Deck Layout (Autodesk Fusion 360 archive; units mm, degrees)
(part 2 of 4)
sketch "Reload Launch Plunger" plane through (0, 0, 8) normal (0, 0, 1) x axis (-1, 0, 0)
  line L1 (-360.8217, -46.399) -> (-358.0535, -46.4059)
  line L2 (-363.9178, -46.3914) -> (-361.0138, -46.3986)
  line L3 (-361.0035, -43.4046) -> (-362.68, -43.397)
  line L4 (-358.0433, -43.4179) -> (-360.8112, -43.4054)
  line L5 (-360.8495, -54.399) -> (-358.0816, -54.4058)
  line L6 (-363.9457, -54.3914) -> (-361.0418, -54.3985)
  line L7 (-361.0313, -51.4045) -> (-363.9352, -51.3914)
  line L8 (-358.071, -51.4179) -> (-360.8392, -51.4054)
  line L9 (-337.909, -43.4822) -> (-343.909, -43.4612)
  line L10 (-340.8631, -46.4708) -> (-337.92, -46.4822)
  line L11 (-343.8396, -46.4594) -> (-340.9768, -46.4704)
  line L12 (-343.9473, -54.4612) -> (-337.9474, -54.4821)
  line L13 (-341.0041, -51.4729) -> (-343.9361, -51.4612)
  line L14 (-338.0323, -51.4848) -> (-340.8681, -51.4735)
  line L15 (-332.4666, -38.0012) -> (-332.3898, -38.0014)
  line L16 (-332.4666, -35.9861) -> (-332.4666, -38.0012)
  line L17 (-369.4666, -35.9861) -> (-332.4666, -35.9861)
  line L18 (-369.4666, -62.0013) -> (-369.4666, -35.9861)
  line L19 (-332.4666, -62.0013) -> (-369.4666, -62.0013)
  line L20 (-332.4666, -60.0013) -> (-332.4666, -62.0013)
  line L21 (-332.3898, -38.0014) -> (-332.4666, -60.0013)
  line L22 (-369.5336, -53.1093) -> (-390.5336, -53.1093)
  line L23 (-390.5336, -45.1093) -> (-369.5336, -45.1093)
  line L24 (-371.5336, -45.1093) -> (-390.5336, -45.1093)
  line L25 (-384.5336, -45.1093) -> (-384.5336, -53.1093)
  line L26 (-387.5336, -45.1093) -> (-387.5336, -53.1093)
  line L27 (-371.5336, -45.1093) -> (-371.5336, -53.1093)
  line L28 (-384.5336, -45.1093) -> (-384.5336, -53.1093)
  line L29 (-390.5336, -53.1093) -> (-390.5336, -45.1093)
  line L30 (-369.5336, -45.1093) -> (-369.5336, -53.1093)
  line L31 (-371.5336, -53.1093) -> (-390.5336, -53.1093)
  line L32 (-332.4666, -35.9861) -> (-332.4666, -38.0012)
  line L33 (-361.0035, -43.4046) -> (-362.68, -43.397)
  line L34 (-332.4666, -38.0012) -> (-332.3898, -38.0014)
  line L35 (-358.071, -51.4179) -> (-360.8392, -51.4054)
  line L36 (-338.0323, -51.4848) -> (-340.8681, -51.4735)
  line L37 (-361.0313, -51.4045) -> (-363.9352, -51.3914)
  line L38 (-387.5336, -45.1093) -> (-387.5336, -53.1093)
  line L39 (-369.5336, -53.1093) -> (-390.5336, -53.1093)
  line L40 (-390.5336, -53.1093) -> (-390.5336, -45.1093)
  line L41 (-360.8217, -46.399) -> (-358.0535, -46.4059)
  line L42 (-337.909, -43.4822) -> (-343.909, -43.4612)
  line L43 (-332.4666, -62.0013) -> (-369.4666, -62.0013)
  line L44 (-369.4666, -35.9861) -> (-332.4666, -35.9861)
  line L45 (-332.3898, -38.0014) -> (-332.4666, -60.0013)
  line L46 (-360.8495, -54.399) -> (-358.0816, -54.4058)
  line L47 (-343.9473, -54.4612) -> (-337.9474, -54.4821)
  line L48 (-340.8631, -46.4708) -> (-337.92, -46.4822)
  line L49 (-369.4666, -62.0013) -> (-369.4666, -35.9861)
  line L50 (-363.9178, -46.3914) -> (-361.0138, -46.3986)
  line L51 (-358.0433, -43.4179) -> (-360.8112, -43.4054)
  line L52 (-341.0041, -51.4729) -> (-343.9361, -51.4612)
  line L53 (-363.9457, -54.3914) -> (-361.0418, -54.3985)
  line L54 (-343.8396, -46.4594) -> (-340.9768, -46.4704)
  line L55 (-332.4666, -60.0013) -> (-332.4666, -62.0013)
  line L56 (-387.5336, -45.1093) -> (-387.5336, -53.1093)
  line L57 (-384.5336, -45.1093) -> (-384.5336, -53.1093)
  line L58 (-371.5336, -53.1093) -> (-390.5336, -53.1093)
  line L59 (-369.5336, -53.1093) -> (-390.5336, -53.1093)
  line L60 (-371.5336, -45.1093) -> (-371.5336, -53.1093)
  line L61 (-384.5336, -45.1093) -> (-384.5336, -53.1093)
  line L62 (-390.5336, -45.1093) -> (-369.5336, -45.1093)
  line L63 (-387.5336, -45.1093) -> (-387.5336, -53.1093)
  line L64 (-390.5336, -53.1093) -> (-390.5336, -45.1093)
  line L65 (-390.5336, -53.1093) -> (-390.5336, -45.1093)
  line L66 (-369.5336, -53.1093) -> (-390.5336, -53.1093)
  line L67 (-371.5336, -45.1093) -> (-390.5336, -45.1093)
  line L68 (-418, -48.8509) -> (-390.6679, -48.8509)
  arc A1 centre (-360.9141, -44.9019) radius 1.5 clockwise from (-360.8217, -46.399) to (-361.0138, -46.3986)
  arc A2 centre (-363.9141, -44.8914) radius 1.5 clockwise from (-363.9178, -46.3914) to (-365.3409, -44.4285)
  arc A3 centre (-364.4071, -42.8897) radius 1.8 clockwise from (-365.3409, -44.4285) to (-362.68, -43.397)
  arc A4 centre (-360.9141, -44.9019) radius 1.5 clockwise from (-361.0035, -43.4046) to (-360.8112, -43.4054)
  arc A5 centre (-357.9141, -44.9124) radius 1.5 clockwise from (-358.0433, -43.4179) to (-358.0535, -46.4059)
  arc A6 centre (-357.942, -52.9123) radius 1.5 clockwise from (-358.071, -51.4179) to (-358.0816, -54.4058)
  arc A7 centre (-360.942, -52.9018) radius 1.5 clockwise from (-360.8495, -54.399) to (-361.0418, -54.3985)
  arc A8 centre (-363.942, -52.8914) radius 1.5 clockwise from (-363.9457, -54.3914) to (-363.9352, -51.3914)
  arc A9 centre (-360.942, -52.9018) radius 1.5 clockwise from (-361.0313, -51.4045) to (-360.8392, -51.4054)
  circle C1 centre (-348.9491, -54.9437) radius 1.8
  arc A10 centre (-343.9142, -44.9612) radius 1.5 clockwise from (-343.8396, -46.4594) to (-343.909, -43.4612)
  arc A11 centre (-337.9142, -44.9822) radius 1.5 clockwise from (-337.909, -43.4822) to (-337.92, -46.4822)
  arc A12 centre (-340.9142, -44.9717) radius 1.5 clockwise from (-340.8631, -46.4708) to (-340.9768, -46.4704)
  arc A13 centre (-343.9421, -52.9612) radius 1.5 clockwise from (-343.9473, -54.4612) to (-343.9361, -51.4612)
  arc A14 centre (-340.9421, -52.9717) radius 1.5 clockwise from (-341.0041, -51.4729) to (-340.8681, -51.4735)
  arc A15 centre (-337.9421, -52.9821) radius 1.5 clockwise from (-338.0323, -51.4848) to (-337.9474, -54.4821)
  arc A16 centre (-340.9142, -44.9717) radius 1.5 clockwise from (-340.8631, -46.4708) to (-340.9768, -46.4704)
  circle C2 centre (-348.9491, -54.9437) radius 1.8
  arc A17 centre (-343.9421, -52.9612) radius 1.5 clockwise from (-343.9473, -54.4612) to (-343.9361, -51.4612)
  arc A18 centre (-360.9141, -44.9019) radius 1.5 clockwise from (-360.8217, -46.399) to (-361.0138, -46.3986)
  arc A19 centre (-340.9421, -52.9717) radius 1.5 clockwise from (-341.0041, -51.4729) to (-340.8681, -51.4735)
  arc A20 centre (-360.942, -52.9018) radius 1.5 clockwise from (-361.0313, -51.4045) to (-360.8392, -51.4054)
  arc A21 centre (-364.4071, -42.8897) radius 1.8 clockwise from (-365.3409, -44.4285) to (-362.68, -43.397)
  arc A22 centre (-360.9141, -44.9019) radius 1.5 clockwise from (-361.0035, -43.4046) to (-360.8112, -43.4054)
  arc A23 centre (-360.942, -52.9018) radius 1.5 clockwise from (-360.8495, -54.399) to (-361.0418, -54.3985)
  arc A24 centre (-357.9141, -44.9124) radius 1.5 clockwise from (-358.0433, -43.4179) to (-358.0535, -46.4059)
  arc A25 centre (-337.9421, -52.9821) radius 1.5 clockwise from (-338.0323, -51.4848) to (-337.9474, -54.4821)
  arc A26 centre (-363.9141, -44.8914) radius 1.5 clockwise from (-363.9178, -46.3914) to (-365.3409, -44.4285)
  arc A27 centre (-363.942, -52.8914) radius 1.5 clockwise from (-363.9457, -54.3914) to (-363.9352, -51.3914)
  arc A28 centre (-357.942, -52.9123) radius 1.5 clockwise from (-358.071, -51.4179) to (-358.0816, -54.4058)
  arc A29 centre (-343.9142, -44.9612) radius 1.5 clockwise from (-343.8396, -46.4594) to (-343.909, -43.4612)
  arc A30 centre (-337.9142, -44.9822) radius 1.5 clockwise from (-337.909, -43.4822) to (-337.92, -46.4822)
  point P59 (-390.5336, -45.1093)
  point P68 (-390.5336, -45.1093)
  point P58 (-390.5336, -53.1093)
  point P70 (-390.5336, -53.1093)
  point P64 (-390.5336, -45.1093)
  point P55 (-387.5336, -53.1093)
  point P63 (-387.5336, -53.1093)
  point P54 (-387.5336, -45.1093)
  point P67 (-387.5336, -45.1093)
  point P56 (-384.5336, -53.1093)
  point P72 (-384.5336, -53.1093)
  point P57 (-384.5336, -45.1093)
  point P65 (-384.5336, -45.1093)
  point P135 (-390.5336, -45.1093)
  point P144 (-390.5336, -45.1093)
  point P134 (-390.5336, -53.1093)
  point P146 (-390.5336, -53.1093)
  point P140 (-390.5336, -45.1093)
  point P131 (-387.5336, -53.1093)
  point P139 (-387.5336, -53.1093)
  point P130 (-387.5336, -45.1093)
  point P143 (-387.5336, -45.1093)
  point P132 (-384.5336, -53.1093)
  point P148 (-384.5336, -53.1093)
  point P133 (-384.5336, -45.1093)
  point P141 (-384.5336, -45.1093)
  point P129 (-390.6679, -48.8509)
  point P154 (-390.6679, -48.8509)
  coincident P59 P68
  coincident P58 P70
  perpendicular L29 L31
  perpendicular L22 L27
  coincident P59 P64
  perpendicular L24 L27
  coincident P55 P63
  coincident P54 P67
  coincident P56 P72
  coincident P57 P65
  coincident P135 P144
  coincident P134 P146
  perpendicular L58 L65
  perpendicular L59 L60
  coincident P135 P140
  perpendicular L60 L67
  coincident P131 P139
  coincident P130 P143
  coincident P132 P148
  coincident P133 P141
  coincident P129 P154
  perpendicular L29 L68
extrude "Extrude19" new body sketch "Reload Launch Plunger" profile of L1 A1 L2 A2 A3 L3 A4 L4 A5 A6 L5 A7 L6 A8 L7 A9 L8 C1 A10 L9 A11 L10 A12 L11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 along normal blind 22 bodies "Z Reload Plunger"
sketch "Reload Launch Solenoid Plunger" plane through (369.4666, 0, 0) normal (1, 0, 0) x axis (0, 1, 0)
  line L1 (62.0013, 8) -> (35.9861, 8)
  line L2 (62.0013, 30) -> (62.0013, 8)
  line L3 (35.9861, 30) -> (62.0013, 30)
  line L4 (35.9861, 8) -> (35.9861, 30)
  circle C1 centre (48.9937, 19) radius 4
  dimension "d134" diameter C1 = 8
extrude "Extrude20" add sketch "Reload Launch Solenoid Plunger" profile of C1 along normal blind 21
extrude "Extrude21" cut sketch "Bottom Runways" along normal blind 30
extrude "Extrude22" cut sketch "Bottom Runways" blind 30 from offset 6
extrude "Extrude23" cut sketch "Bottom Runways" along normal blind 30
extrude "Extrude24" cut sketch "Bottom Runways" blind 30 from offset 6
extrude "Extrude25" cut sketch "Bottom Runways" along normal blind 30
extrude "Extrude26" cut sketch "Bottom Runways" blind 30 from offset 6
work_axis "WorkAxis1"
extrude "Extrude27" new body sketch "Bottom Runways" blind 1.2 from offset 4.1 bodies "Reload Ball Release Lower Washer"
extrude "Extrude28" add sketch "Bottom Runways" along normal blind 25.6
extrude "Extrude29" add sketch "Bottom Runways" along normal blind 15
extrude "Extrude30" new body sketch "Bottom Runways" blind 13.5 from offset 5.5 bodies "Reload Ball Release Drive"
extrude "Extrude31" add sketch "Bottom Runways" blind 6 from offset 19
extrude "Extrude32" add sketch "Bottom Runways" blind 7.8 from offset 19
sketch "Reload Solenoid Coupling Arm" plane through (0, 0, 19) normal (0, 0, 1) x axis (-1, 0, 0)
  line L1 (-444.88, -53.4852) -> (-387.5956, -53.8589)
  line L2 (-423.127, -44.127) -> (-387.5336, -44.3593)
  line L3 (-398, -53.791) -> (-398, -44.291)
  line L4 (-395, -53.8106) -> (-395, -44.3106)
  line L5 (-440.9582, -46.0106) -> (-425.114, -46.114)
  line L6 (-425.114, -46.114) -> (-423.127, -44.127)
  line L7 (-451, -44) -> (-451, -57.3866)
  line L8 (-451, -44) -> (-446, -39)
  line L9 (-435.7954, -39) -> (-446, -39)
  line L10 (-457.6104, -58.2381) -> (-457.6104, -37.3896)
  line L11 (-447.333, -53.4692) -> (-444.88, -53.4852)
  line L12 (-442.7019, -50) -> (-449.7621, -50)
  line L13 (-384.6635, -53.878) -> (-383.3324, -51.2655)
  line L14 (-384.6635, -53.878) -> (-387.5956, -53.8589)
  line L15 (-444.88, -53.4852) -> (-447.333, -53.4692)
  line L16 (-446.1065, -53.4772) -> (-447.333, -53.4692)
  line L17 (-447.333, -53.4692) -> (-447.9394, -53.4652)
  line L18 (-437.9654, -48.7353) -> (-444.849, -48.7353)
  line L19 (-448.2234, -45.3921) -> (-448.2078, -45.3765)
  line L20 (-457.6104, -34.8442) -> (-453.3534, -30.5668)
  line L21 (-457.6104, -34.8442) -> (-457.6104, -37.3896)
  line L22 (-440.0563, -35.1519) -> (-448.7462, -35.1519)
  line L23 (-446.8964, -30.0697) -> (-446.8096, -29.831)
  circle C1 centre (-444.849, -48.7353) radius 3
  circle C2 centre (-444.849, -48.7353) radius 3.3
  circle C3 centre (-387.5336, -49.1093) radius 1.8
  arc A1 centre (-387.5646, -49.1091) radius 4.7499 clockwise from (-387.5336, -44.3593) to (-383.3324, -51.2655)
  arc A2 centre (-440, -40) radius 15.75 clockwise from (-452.1681, -30) to (-442.002, -24.3778)
  arc A3 centre (-448.7462, -35.1519) radius 4.75 clockwise from (-444.8545, -32.4285) to (-446.0894, -39.0894)
  circle C4 centre (-448.7462, -35.1519) radius 3.25
  circle C5 centre (-453.7462, -62.1519) radius 3.75
  arc A4 centre (-453.7462, -62.1519) radius 5.5 clockwise from (-451, -57.3866) to (-457.6104, -58.2381)
  arc A5 centre (-444.849, -48.7353) radius 5.65 clockwise from (-447.9394, -53.4652) to (-449.6099, -45.6928)
  arc A6 centre (-444.8491, -48.7353) radius 4.75 clockwise from (-448.2078, -45.3765) to (-440.9582, -46.0106)
  arc A7 centre (-448.7673, -46.2313) radius 1 clockwise from (-449.6099, -45.6928) to (-448.2234, -45.3921)
  arc A8 centre (-448.7462, -35.1519) radius 6.5 clockwise from (-453.3534, -30.5668) to (-447.6707, -28.7415)
  arc A9 centre (-448.7462, -35.1519) radius 4.75 clockwise from (-446.3701, -31.0389) to (-444.8545, -32.4285)
  arc A10 centre (-447.8361, -29.7277) radius 1 clockwise from (-447.6707, -28.7415) to (-446.8964, -30.0697)
  arc A11 centre (-445.8699, -30.173) radius 1 clockwise from (-446.3701, -31.0389) to (-446.8096, -29.831)
  point P7 (-387.5956, -53.8589)
  point P10 (-398, -53.791)
  point P11 (-398, -44.291)
  point P12 (-395, -53.8106)
  point P13 (-395, -44.3106)
  point P17 (-448.7462, -35.1519)
  point P18 (-448.7462, -35.1519)
  point P27 (-446.0894, -39.0894)
  point P19 (-453.7462, -62.1519)
  point P29 (-453.7462, -62.1519)
  point P3 (-444.849, -48.7353)
  point P42 (-444.849, -48.7353)
  point P52 (-448.7462, -35.1519)
  point P28 (-448.7462, -35.1519)
  point P54 (-448.7462, -35.1519)
  coincident P7 A1
  vertical L3
  coincident L1 P10
  coincident L2 P11
  vertical L4
  coincident L1 P12
  coincident L2 P13
  coincident P17 P18
  vertical L7
  horizontal L9
  vertical L10
  coincident L8 P27
  concentric A3 C4
  coincident P19 P29
  concentric C5 A4
  tangent L1 A6
  tangent L1 A1
  tangent L11 A6
  horizontal L12
  tangent A1 L13
  tangent A1 L14
  concentric C1 A5
  parallel L11 L15
  parallel L1 L16
  parallel L16 L17
  horizontal L18
  coincident P3 P42
  tangent A5 A7
  tangent A6 L19
  concentric A3 A8
  tangent A8 L20
  parallel L10 L21
  horizontal L22
  coincident P18 P52
  coincident P28 P54
  tangent A8 A10
  tangent L23 A10
  tangent A9 A11
  tangent L23 A11
  dimension "d319" diameter A5 = 11.3
  dimension "d321" radius A7 = 1
  dimension "d338" radius A10 = 1
  dimension "d339" radius A11 = 1
extrude "Extrude33" new body sketch "Reload Solenoid Coupling Arm" profile of C2 A6 L1 L2 L3 L5 L6 blind 7.1 from offset 0.3 bodies "Reload Ball Release Solenoid Coupling"
extrude "Extrude34" add sketch "Reload Solenoid Coupling Arm" profile of L1 L2 L3 L4 along normal blind 7.4 and against normal blind 7.3
extrude "Extrude35" add sketch "Reload Solenoid Coupling Arm" profile of C3 A1 L1 L2 L4 blind 3 from offset 4.4
extrude "Extrude36" add sketch "Reload Solenoid Coupling Arm" profile of C3 A1 L1 L2 L4 blind -3 from offset -4.3
extrude "Extrude37" new body sketch "Bottom Runways" blind 15.5 from offset 3.2 bodies "Reload Ball Release Slide"
extrude "Extrude38" add sketch "Bottom Runways" blind 8.1 from offset 18.7
extrude "Extrude39" new body sketch "Reload Solenoid Coupling Arm" profile of A3 L7 L8 L10 C4 C5 A4 blind 7.1 from offset 0.3 bodies "Reload Ball Release Slide Coupling"
extrude "Extrude40" add sketch "Bottom Runways" blind 15 from offset 18.7
extrude "Extrude41" add sketch "Bottom Runways" blind 7.3 from offset 26.4
extrude "Extrude42" new body sketch "Bottom Runways" profile of L31 L32 L33 L39 L40 blind 27.6 from offset 3.1
fillet "Fillet1" radius 8
chamfer "Chamfer1" distance 3 distance 1.2
fillet "Fillet3" radius 3
fillet "Fillet5" radius 2
sketch "Front panel Plunger" plane through (0, 0, 0) normal (0, -1, 0) x axis (1, 0, 0)
  line L1 (500, 25) -> (500, 0)
  circle C1 centre (487.5, 12.5) radius 6.75
  circle C2 centre (495.5, 20.5) radius 1.75
  circle C3 centre (479.5, 20.5) radius 1.75
  circle C4 centre (495.5, 4.5) radius 1.75
  circle C5 centre (479.5, 4.5) radius 1.75
extrude "Extrude43" cut sketch "Front panel Plunger" profile of C1 against normal blind 12
work_plane "WorkPlane1" AlongDistance 10
sketch "Ball Reloading Plenum" plane through (0, 0, 13) normal (0, 0, 1) x axis (1, 0, 0)
  line L1 (500, 55) -> (500, 55)
  line L2 (500, 35) -> (496.5, 55)
  line L3 (475.0759, 35.4337) -> (478.5, 55)
  line L4 (500, 35) -> (500, 55)
  line L5 (500, 60) -> (500, 55)
  line L6 (475.0759, 59.9858) -> (475.0759, 35.4337)
  arc A1 centre (474.2429, 55.745) radius 4.3218 clockwise from (475.0759, 59.9858) to (478.5, 55)
  arc A2 centre (500.7572, 55.745) radius 4.3218 clockwise from (496.5, 55) to (500, 60)
  tangent A1 L3
work_axis "WorkAxis2"
revolve "Revolve1" sketch "Ball Reloading Plenum" AlongAngle 360
work_plane "WorkPlane2"
sketch "Sketch16" plane through (0, 60, 0) normal (0, -1, 0) x axis (-1, 0, 0)
  line L1 (-475.0759, -25) -> (-475.0759, -3)
  line L2 (-500, -25) -> (-475.0759, -25)
  line L3 (-500, -3) -> (-500, -25)
  line L4 (-475.0152, -3) -> (-475.0759, -25)
  line L5 (-500, 0) -> (-496.5, 0)
  line L6 (-500, 0) -> (-500, -3)
  line L7 (-475.0759, 0) -> (-475.0152, -3)
  line L8 (-500, 0) -> (-475.0759, 0)
  line L9 (-480, -3) -> (-495, -3)
  arc A1 centre (-487.5, -13) radius 12.5 clockwise from (-475.0759, -14.3754) to (-495, -3)
  arc A2 centre (-487.5, -13) radius 12.5 clockwise from (-480.7181, -2.4997) to (-475.0759, -11.6246)
  arc A3 centre (-487.5, -13) radius 12.5 clockwise from (-475.0759, -14.3754) to (-484, -25)
  arc A4 centre (-487.5, -13) radius 12.5 clockwise from (-491, -25) to (-495, -3)
  point P6 (-475.0759, -25)
  point P8 (-475.0759, -25)
  point P7 (-500, -25)
  point P9 (-500, -25)
  point P11 (-475.0152, -3)
  point P12 (-475.0152, -3)
  point P14 (-475.0759, -11.6246)
  point P4 (-487.5, -13)
  point P13 (-487.5, -13)
  point P18 (-484, -25)
  point P3 (-475.0759, -14.3754)
  point P19 (-475.0759, -14.3754)
  point P17 (-487.5, -13)
  point P2 (-495, -3)
  point P21 (-495, -3)
  point P20 (-487.5, -13)
  point P28 (-475.0152, -3)
  point P27 (-475.0759, 0)
  point P29 (-475.0759, 0)
  point P16 (-480, -3)
  point P31 (-480, -3)
  coincident P6 P8
  coincident P7 P9
  coincident P11 P12
  coincident L1 P14
  coincident P4 P13
  coincident L2 P18
  coincident P3 P19
  coincident P4 P17
  coincident P2 P21
  coincident P17 P20
  coincident P11 P28
  coincident P27 P29
  perpendicular L6 L8
  coincident P16 P31
  parallel L8 L9
extrude "Extrude44" add sketch "Sketch16" profile of A1 L1 L2 L3 A2 A3 A4 along normal blind 25
chamfer "Chamfer2" distance 70 distance 2.6
extrude "Extrude45" add sketch "Reload Plunger" profile of L1 L4 L6 L13 L16 L17 L18 L21 L22 L23 L24 L25 L26 A1 L27 A2 A3 A4 C1 L28 L29 L30 L31 L32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 blind 4 from offset 3
extrude "Extrude46" cut sketch "Reload Plunger" profile of L17 A1 L27 A2 A3 A4 C1 L32 L33 A5 C2 L34 A6 C3 C4 L36 A7 A8 A9 A10 A11 A12 L40 C5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 along normal blind 100
extrude "Extrude47" cut sketch "Reload Plunger" profile of A1 L27 A2 A3 C1 L32 L33 C2 L34 C3 C4 L36 A7 L40 C5 L41 C6 A13 C7 C8 L43 L44 C9 L45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 along normal blind 4 bodies "Left Loweer Deck Section (1)"
extrude "Extrude48" new body sketch "Reload Plunger" profile of L1 L4 L6 L13 L16 L17 L18 L21 L22 L23 L24 L25 L26 A1 L27 A2 A3 A4 C1 L28 L29 L30 L31 L32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 blind 22 from offset 7.1 bodies "Reload Solenoid"
sketch "Sketch17" plane through (107.1589, 52.7287, 0) normal (0.8973, 0.4415, 0) x axis (-0.4415, 0.8973, 0)
  line L1 (-0.1972, 7.1) -> (-26.2124, 7.1)
  line L2 (-0.1972, 29.1) -> (-0.1972, 7.1)
  line L3 (-26.2124, 29.1) -> (-0.1972, 29.1)
  line L4 (-26.2124, 7.1) -> (-26.2124, 29.1)
  circle C1 centre (-13.2048, 18.1) radius 4
  dimension "d246" diameter C1 = 8
extrude "Extrude49" add sketch "Sketch17" profile of C1 along normal blind 21
extrude "Extrude50" new body sketch "Reload Flipper" blind 5 from offset 3.1 bodies "Reload Load Coupling Bushing"
extrude "Extrude51" new body sketch "Reload Flipper" profile of C1 A1 A2 C2 A3 L2 L3 L4 C3 L5 A4 L6 A5 A6 A7 L7 blind 8 from offset 8.2 bodies "Reload Load Flipper"
work_axis "WorkAxis3"
extrude "Extrude52" new body sketch "reload coupling" profile of L1 L2 L5 L6 L7 L8 L9 L10 L12 blind 8 from offset 14.1 bodies "Reload Load Coupling"
extrude "Extrude53" new body sketch "reload coupling" profile of L1 L2 L3 L4 C1 A1 A2 L10 L12 blind 3 from offset 10.7
extrude "Extrude54" add sketch "reload coupling" profile of L1 L2 L10 L12 blind 5 from offset 10.7
extrude "Extrude55" new body sketch "reload coupling" profile of L1 L2 L3 L4 C1 A1 A2 L10 L12 blind 3 from offset 22.4
extrude "Extrude56" add sketch "reload coupling" profile of L1 L2 L10 L12 blind 1 from offset 22
extrude "Extrude57" add sketch "reload coupling" profile of A3 L1 L2 C2 L5 L6 L7 L8 L9 blind 5.7 from offset 16.4
chamfer "Chamfer3" distance 2 distance 2
chamfer "Chamfer5" distance 38 distance 2.6
move "Move10"
move "Move11"
sketch "Reload Launch Retainer" plane through (0, 0, 17) normal (0, 0, 1) x axis (-1, 0, 0)
  circle C1 centre (-185.8525, -49.8361) radius 1.4
  circle C2 centre (-185.8525, -49.8361) radius 10
  circle C3 centre (-185.8525, -49.8361) radius 1.75
  concentric C1 C2
  concentric C2 C3
  dimension "d282" diameter C1 = 2.8
  dimension "d283" diameter C2 = 20
  dimension "d284" diameter C3 = 3.5
extrude "Extrude58" cut sketch "Reload Launch Retainer" profile of C1 against normal blind 12
extrude "Extrude59" new body sketch "Reload Launch Retainer" profile of C2 C3 blind 2 from offset 0.2 bodies "Reload Load Retaining Washer"
extrude "Extrude60" cut sketch "Bottom Runways" along normal blind 10
sketch "Sketch19" plane through (0, 0, 0) normal (1, 0, 0) x axis (0, 1, 0)
extrude "Extrude61" cut sketch "Bottom Runways" along normal blind 10
sketch "Reload Ball Release Slide Gusset" plane through (0, 0, 33.7) normal (0, 0, 1) x axis (-1, 0, 0)
  line L1 (-437.4865, -56.1294) -> (-437.4865, -121.6401)
  line L2 (-441.9908, -73.2037) -> (-441.9908, -56.2022)
  line L3 (-441.9885, -121.6401) -> (-441.9885, -83.2046)
  line L4 (-441.9885, -121.6401) -> (-437.4865, -121.6401)
  line L5 (-441.9908, -56.2022) -> (-441.9885, -121.6401)
  line L6 (-437.4865, -56.1294) -> (-437.4865, -121.6401)
  line L7 (-441.9908, -56.2022) -> (-437.4865, -56.1294)
  line L8 (-444.1098, -119.5188) -> (-441.9885, -121.6401)
  line L9 (-411.5261, -121.6401) -> (-441.9885, -121.6401)
  line L10 (-435.3652, -119.5188) -> (-437.4865, -121.6401)
  line L11 (-367.2232, -121.6401) -> (-437.4865, -121.6401)
  line L12 (-437.4865, -56.1294) -> (-435.3652, -58.2507)
  line L13 (-441.9908, -56.2022) -> (-444.1121, -58.3235)
  line L14 (-444.1098, -119.5188) -> (-444.1121, -58.3235)
  line L15 (-435.3652, -119.5188) -> (-435.3652, -58.2507)
  line L16 (-441.9885, -83.2046) -> (-441.9908, -73.2037)
  line L17 (-437.4865, -121.6401) -> (-441.9885, -121.6401)
  arc A1 centre (-440, -40) radius 16.3241 clockwise from (-437.4865, -56.1294) to (-441.9908, -56.2022)
  point P2 (-437.4865, -121.6401)
  point P9 (-437.4865, -121.6401)
  point P8 (-441.9885, -121.6401)
  point P10 (-441.9885, -121.6401)
  point P4 (-441.9908, -56.2022)
  point P11 (-441.9908, -56.2022)
  point P12 (-437.4865, -121.6401)
  point P3 (-437.4865, -56.1294)
  point P13 (-437.4865, -56.1294)
  coincident P2 P9
  coincident P8 P10
  coincident P4 P11
  coincident P2 P12
  coincident P3 P13
  horizontal L9
  horizontal L11
  parallel L6 L15
combine "Combine1"
fillet "Fillet6" radius 2
combine "Combine3" bodies "Reload Ball Release Slide (1)", "Reload Ball Release Slide Coupling"
extrude "Extrude63" add sketch "Bottom Runways" blind 26.7 from offset 3.1
fillet "Fillet8" radius 1.2
combine "Combine4"
fillet "Fillet9" radius 1.2
fillet "Fillet10" radius 2
extrude "Extrude64" add sketch "Bottom Runways" blind 4.7 from offset 29
fillet "Fillet12" radius 8
fillet "Fillet13" radius 4
fillet "Fillet14" radius 1.4
extrude "Extrude65" cut sketch "Front panel Plunger" profile of C2 C3 C4 C5 against normal blind 20
chamfer "Chamfer8" distance 70
chamfer "Chamfer9" distance 3.3 distance 3.3
sketch "Reload Washers" plane through (0, 0, 26.8) normal (0, 0, 1) x axis (-1, 0, 0)
  circle C1 centre (-453.7462, -62.1519) radius 1.4
  circle C2 centre (-453.7462, -62.1519) radius 4.75
  circle C3 centre (-453.7462, -62.1519) radius 1.9
  concentric C1 C2
  concentric C2 C3
extrude "Extrude66" new body sketch "Reload Washers" profile of C2 C3 blind 1.5 from offset 0.1 bodies "Reload Ball Release Washer"
sketch "Top Runways" plane through (0, 0, 0) normal (0, 0, 1) x axis (1, 0, 0)
  line L1 (418.7386, 900) -> (350, 900)
  line L2 (500, 818.7386) -> (500, 750)
  line L3 (250, 900) -> (250, 0)
  line L4 (221.0012, 561.9864) -> (279.0012, 561.9875)
  line L5 (221.0105, 597.9864) -> (279.0105, 597.9874)
  line L6 (233.4571, 597.9866) -> (233.4571, 597.9865)
  line L7 (221.0012, 561.9864) -> (221.0105, 597.9864)
  line L8 (279.0012, 561.9875) -> (279.0105, 597.9874)
  line L9 (329.0012, 651.9875) -> (329.0105, 687.9874)
  line L10 (271.0012, 651.9864) -> (329.0012, 651.9875)
  line L11 (283.4571, 687.9866) -> (283.4571, 687.9865)
  line L12 (271.0012, 651.9864) -> (271.0105, 687.9864)
  line L13 (271.0105, 687.9864) -> (329.0105, 687.9874)
  line L14 (171.0105, 687.9864) -> (229.0105, 687.9874)
  line L15 (171.0012, 651.9864) -> (229.0012, 651.9875)
  line L16 (183.4571, 687.9866) -> (183.4571, 687.9865)
  line L17 (171.0012, 651.9864) -> (171.0105, 687.9864)
  line L18 (229.0012, 651.9875) -> (229.0105, 687.9874)
  line L19 (30, 1800) -> (30, 551)
  line L20 (30, 751.0007) -> (96.5, 751)
  line L21 (30, 899) -> (30, 751.0007)
  line L22 (30, 899) -> (175, 899)
  curve K1 (96.5, 751) -> (175, 899)
  circle C1 centre (438.5624, 880.2435) radius 2
  arc A1 centre (350, 750) radius 150 clockwise from (350, 900) to (500, 750)
  circle C2 centre (492.7435, 816.5624) radius 5
  circle C3 centre (492.7435, 816.5624) radius 2
  circle C4 centre (438.5624, 880.2435) radius 5
  arc A2 centre (350, 750) radius 165 clockwise from (418.7386, 900) to (500, 818.7386)
  circle C5 centre (250, 810) radius 2.25
  circle C6 centre (250, 760) radius 2.25
  circle C7 centre (290, 760) radius 2.25
  circle C8 centre (290, 810) radius 2.25
  circle C9 centre (330, 760) radius 2.25
  circle C10 centre (330, 810) radius 2.25
  circle C11 centre (210, 760) radius 2.25
  circle C12 centre (170, 760) radius 2.25
  circle C13 centre (170, 810) radius 2.25
  circle C14 centre (210, 810) radius 2.25
  circle C15 centre (300, 670) radius 42.5
  circle C16 centre (200, 670) radius 42.5
  circle C17 centre (250, 580) radius 42.5
  circle C18 centre (227.0148, 593.9876) radius 1.75
  circle C19 centre (227.0148, 565.9876) radius 1.75
  circle C20 centre (273.0148, 593.9876) radius 1.75
  circle C21 centre (273.0148, 565.9876) radius 1.75
  circle C22 centre (277.0148, 655.9876) radius 1.75
  circle C23 centre (323.0148, 683.9876) radius 1.75
  circle C24 centre (277.0148, 683.9876) radius 1.75
  circle C25 centre (323.0148, 655.9876) radius 1.75
  circle C26 centre (177.0148, 683.9876) radius 1.75
  circle C27 centre (223.0148, 655.9876) radius 1.75
  circle C28 centre (223.0148, 683.9876) radius 1.75
  circle C29 centre (177.0148, 655.9876) radius 1.75
  circle C30 centre (300, 670) radius 13
  circle C31 centre (200, 670) radius 13
  circle C32 centre (250, 580) radius 13
  circle C33 centre (45, 765) radius 4
  circle C34 centre (45, 765) radius 2.25
  circle C35 centre (45, 880) radius 2.25
  circle C36 centre (45, 880) radius 4
  circle C37 centre (95, 880) radius 4
  circle C38 centre (95, 880) radius 2.25
  point P4 (350, 750)
  point P5 (350, 750)
  point P33 (221.0012, 561.9864)
  point P31 (279.0012, 561.9875)
  point P32 (233.4571, 597.9866)
  point P40 (271.0012, 651.9864)
  point P41 (329.0012, 651.9875)
  point P42 (283.4571, 687.9866)
  point P54 (171.0012, 651.9864)
  point P58 (229.0012, 651.9875)
  point P56 (183.4571, 687.9866)
  point P70 (30, 751.0007)
  point P71 (30, 899)
  coincident P4 P5
  coincident P33 L7
  coincident P31 L4
  coincident P32 L5
  coincident P40 L12
  coincident P41 L10
  coincident P42 L13
  coincident P54 L17
  coincident P58 L15
  coincident P56 L14
  concentric C15 C30
  coincident L19 P70
  coincident L19 P71
  concentric C33 C34
  concentric C35 C36
  concentric C37 C38
  dimension "d425" diameter C5 = 4.5
  dimension "d426" diameter C6 = 4.5
  dimension "d427" diameter C8 = 4.5
  dimension "d428" diameter C7 = 4.5
  dimension "d429" diameter C10 = 4.5
  dimension "d430" diameter C9 = 4.5
  dimension "d431" diameter C13 = 4.5
  dimension "d432" diameter C12 = 4.5
  dimension "d433" diameter C14 = 4.5
  dimension "d434" diameter C11 = 4.5
  dimension "d435" diameter C15 = 85
  dimension "d436" diameter C16 = 85
  dimension "d437" diameter C17 = 85
  dimension "d536" diameter C33 = 8
  dimension "d537" diameter C34 = 4.5
  dimension "d540" diameter C36 = 8
  dimension "d541" diameter C35 = 4.5
  dimension "d542" diameter C37 = 8
  dimension "d543" diameter C38 = 4.5
extrude "Extrude70" new body sketch "Top Runways" profile of L1 A1 C2 L2 C4 A2 along normal blind 25 bodies "Top Right Corner"
extrude "Extrude71" add sketch "Top Runways" profile of C1 C2 C3 C4 along normal blind 4
fillet "Fillet17" radius 0.2
fillet "Fillet18" radius 2
sketch "Side Alleys" plane through (0, 0, 0) normal (0, 0, 1) x axis (1, 0, 0)
  line L1 (428, 247.6) -> (428, 360.3398)
  line L2 (438, 225) -> (336.5156, 172.0071)
  line L3 (438, 360.3397) -> (438, 225)
  line L4 (428, 247.6) -> (325.1003, 193.868)
  line L5 (427.8841, 247.8619) -> (428, 247.6)
  line L6 (250, 300) -> (250, 150)
  line L7 (62, 360.3397) -> (62, 225)
  line L8 (72, 247.6) -> (174.8997, 193.868)
  line L9 (72, 247.6) -> (72, 360.3398)
  line L10 (72.1159, 247.8619) -> (72, 247.6)
  line L11 (62, 225) -> (163.4844, 172.0071)
  circle C1 centre (348.3539, 192.2903) radius 2.25
  circle C2 centre (433, 235) radius 2.25
  circle C3 centre (433, 350) radius 2.25
  arc A1 centre (323.2371, 178.9842) radius 15 clockwise from (325.1003, 193.868) to (336.5156, 172.0071)
  circle C4 centre (348.3539, 192.2903) radius 4
  circle C5 centre (433, 235) radius 4
  circle C6 centre (433, 350) radius 4
  arc A2 centre (433, 369) radius 10 clockwise from (438, 360.3397) to (428, 360.3398)
  circle C7 centre (151.6461, 192.2903) radius 4
  circle C8 centre (67, 350) radius 2.25
  circle C9 centre (67, 235) radius 4
  arc A3 centre (67, 369) radius 10 clockwise from (72, 360.3398) to (62, 360.3397)
  circle C10 centre (151.6461, 192.2903) radius 2.25
  arc A4 centre (176.7629, 178.9842) radius 15 clockwise from (163.4844, 172.0071) to (174.8997, 193.868)
  circle C11 centre (67, 235) radius 2.25
  circle C12 centre (67, 350) radius 4
  circle C13 centre (433, 369) radius 9
  circle C14 centre (67, 369) radius 9
  circle C15 centre (433, 369) radius 2.25
  circle C16 centre (67, 369) radius 2.25
  point P6 (438, 225)
  point P14 (438, 225)
  point P2 (438, 225)
  point P30 (62, 225)
  point P3 (428, 247.6)
  point P22 (72, 247.6)
  point P37 (62, 225)
  point P7 (325.1003, 193.868)
  point P29 (174.8997, 193.868)
  point P10 (336.5156, 172.0071)
  point P28 (163.4844, 172.0071)
  point P12 (428, 247.6)
  point P32 (72, 247.6)
  point P13 (427.8841, 247.8619)
  point P34 (72.1159, 247.8619)
  point P27 (62, 225)
  point P18 (428, 360.3398)
  point P31 (72, 360.3398)
  point P19 (438, 360.3397)
  point P26 (62, 360.3397)
  coincident P6 P14
  coincident P2 P6
  vertical L6
  symmetric P2 L6 P30
  symmetric P3 L6 P22
  symmetric P6 L6 P37
  symmetric P7 L6 P29
  symmetric P10 L6 P28
  symmetric P12 L6 P32
  symmetric P13 L6 P34
  symmetric P14 L6 P27
  symmetric C1 L6 C10
  symmetric C2 L6 C11
  symmetric C3 L6 C8
  symmetric A1 L6 A4
  symmetric C4 L6 C7
  symmetric C5 L6 C9
  symmetric C6 L6 C12
  symmetric A2 L6 A3
  symmetric P18 L6 P31
  symmetric P19 L6 P26
  concentric A2 C13
  concentric A3 C14
  concentric A2 C15
  concentric A3 C16
  dimension "d399" diameter C6 = 8
  dimension "d400" diameter C3 = 4.5
  dimension "d401" diameter C5 = 8
  dimension "d402" diameter C2 = 4.5
  dimension "d403" diameter C4 = 8
  dimension "d404" diameter C1 = 4.5
  dimension "d406" radius A2 = 10
  dimension "d467" diameter C13 = 18
  dimension "d468" diameter C14 = 18
  dimension "d470" diameter C15 = 4.5
  dimension "d471" diameter C16 = 4.5
extrude "Extrude72" new body sketch "Side Alleys" profile of L1 L2 L3 A1 C4 C5 L4 C6 A2 along normal blind 25 bodies "Outer Runway Right"
extrude "Extrude73" add sketch "Side Alleys" profile of C1 C2 C3 C4 C5 C6 along normal blind 4
fillet "Fillet19" radius 1.4
fillet "Fillet20" radius 1.4
fillet "Fillet21" radius 0.8
extrude "Extrude74" new body sketch "Side Alleys" profile of C7 C9 L7 A3 L8 L9 L11 A4 C12 along normal blind 25 bodies "Outer Runway Left"
extrude "Extrude75" add sketch "Side Alleys" profile of C7 C8 C9 C10 C11 C12 along normal blind 4
fillet "Fillet22" radius 2
fillet "Fillet23" radius 0.8
sketch "Round_For_Bumper" plane through (0, 0, 0) normal (0, 0, 1) x axis (1, 0, 0)
  line L1 (136.7259, 96.0353) -> (137.5213, 96.3248)
  line L2 (136.473, 95.4929) -> (136.7259, 96.0353)
  line L3 (137.0154, 95.2399) -> (136.473, 95.4929)
  line L4 (137.8108, 95.5294) -> (137.0154, 95.2399)
  line L5 (136.9072, 94.2999) -> (136.7625, 94.6975)
  line L6 (136.8348, 94.4987) -> (136.9072, 94.2999)
  line L7 (138.0279, 94.9329) -> (136.8348, 94.4987)
  line L8 (137.7567, 95.0594) -> (138.0279, 94.9329)
  line L9 (137.3232, 93.7757) -> (137.1243, 93.7033)
  line L10 (137.3955, 93.5769) -> (137.3232, 93.7757)
  line L11 (137.1967, 93.5045) -> (137.3955, 93.5769)
  line L12 (137.1243, 93.7033) -> (137.1967, 93.5045)
  line L13 (138.7516, 92.9445) -> (138.4804, 93.071)
  line L14 (138.8963, 92.5469) -> (138.7516, 92.9445)
  line L15 (138.7698, 92.2757) -> (138.8963, 92.5469)
  line L16 (137.9745, 91.9862) -> (138.7698, 92.2757)
  line L17 (137.7033, 92.1126) -> (137.9745, 91.9862)
  line L18 (137.5585, 92.5103) -> (137.7033, 92.1126)
  line L19 (137.685, 92.7815) -> (137.5585, 92.5103)
  line L20 (138.4804, 93.071) -> (137.685, 92.7815)
  line L21 (139.4402, 96.8205) -> (139.3137, 96.5493)
  line L22 (139.2954, 97.2181) -> (139.4402, 96.8205)
  line L23 (139.0242, 97.3446) -> (139.2954, 97.2181)
  line L24 (138.2289, 97.0551) -> (139.0242, 97.3446)
  line L25 (138.1024, 96.7839) -> (138.2289, 97.0551)
  line L26 (138.2472, 96.3862) -> (138.1024, 96.7839)
  line L27 (138.5184, 96.2598) -> (138.2472, 96.3862)
  line L28 (138.609, 95.3921) -> (138.4643, 95.7897)
  line L29 (138.5366, 95.5909) -> (138.609, 95.3921)
  line L30 (139.332, 95.8804) -> (138.5366, 95.5909)
  line L31 (139.2596, 96.0792) -> (139.332, 95.8804)
  line L32 (138.8261, 94.7955) -> (139.6215, 95.085)
  line L33 (139.2238, 94.9403) -> (138.8261, 94.7955)
  line L34 (139.495, 94.8138) -> (139.2238, 94.9403)
  line L35 (139.7662, 94.6873) -> (139.495, 94.8138)
  line L36 (139.8386, 94.4885) -> (139.7662, 94.6873)
  line L37 (140.1281, 93.6932) -> (140.3452, 93.0967)
  line L38 (139.8569, 93.8196) -> (140.1281, 93.6932)
  line L39 (139.4592, 93.6749) -> (139.8569, 93.8196)
  line L40 (139.3327, 93.4037) -> (139.4592, 93.6749)
  line L41 (139.5498, 92.8072) -> (139.3327, 93.4037)
  line L42 (139.8393, 92.0118) -> (139.6946, 92.4095)
  line L43 (139.7669, 92.2107) -> (139.8393, 92.0118)
  line L44 (140.96, 92.6449) -> (139.7669, 92.2107)
  line L45 (140.8876, 92.8437) -> (140.96, 92.6449)
  line L46 (140.1288, 91.2165) -> (140.2735, 90.8188)
  line L47 (140.2553, 91.4877) -> (140.1288, 91.2165)
  line L48 (140.6529, 91.6324) -> (140.2553, 91.4877)
  line L49 (140.9242, 91.506) -> (140.6529, 91.6324)
  line L50 (141.0689, 91.1083) -> (140.9242, 91.506)
  line L51 (140.9424, 90.8371) -> (141.0689, 91.1083)
  line L52 (140.7436, 90.7647) -> (140.9424, 90.8371)
  line L53 (140.4541, 91.5601) -> (140.7436, 90.7647)
  line L54 (140.9249, 89.0293) -> (142.1179, 89.4635)
  line L55 (141.2144, 88.2339) -> (140.9249, 89.0293)
  line L56 (142.5521, 88.2705) -> (142.8416, 87.4751)
  line L57 (141.3591, 87.8362) -> (142.5521, 88.2705)
  line L58 (141.6486, 87.0409) -> (141.3591, 87.8362)
  line L59 (142.1004, 87.6557) -> (141.9556, 88.0534)
  line L60 (141.7933, 86.6432) -> (142.9864, 87.0774)
  line L61 (142.0104, 86.0467) -> (141.7933, 86.6432)
  line L62 (142.2816, 85.9202) -> (142.0104, 86.0467)
  line L63 (143.077, 86.2097) -> (142.2816, 85.9202)
  line L64 (143.2035, 86.4809) -> (143.077, 86.2097)
  line L65 (142.9864, 87.0774) -> (143.2035, 86.4809)
  line L66 (143.6377, 85.2879) -> (143.5112, 85.0167)
  line L67 (143.4929, 85.6856) -> (143.6377, 85.2879)
  line L68 (143.2217, 85.812) -> (143.4929, 85.6856)
  line L69 (143.0229, 85.7397) -> (143.2217, 85.812)
  line L70 (142.8964, 85.4685) -> (143.0229, 85.7397)
  line L71 (143.0412, 85.0708) -> (142.8964, 85.4685)
  line L72 (142.9147, 84.7996) -> (143.0412, 85.0708)
  line L73 (142.7159, 84.7272) -> (142.9147, 84.7996)
  line L74 (142.4447, 84.8537) -> (142.7159, 84.7272)
  line L75 (142.2999, 85.2514) -> (142.4447, 84.8537)
  line L76 (142.4264, 85.5226) -> (142.2999, 85.2514)
  line L77 (141.254, 98.1847) -> (139.8224, 97.6636)
  line L78 (141.5145, 97.4688) -> (141.254, 98.1847)
  line L79 (141.3628, 97.1434) -> (141.5145, 97.4688)
  line L80 (140.8856, 96.9697) -> (141.3628, 97.1434)
  line L81 (140.5601, 97.1215) -> (140.8856, 96.9697)
  line L82 (140.2996, 97.8373) -> (140.5601, 97.1215)
  line L83 (140.5171, 95.7548) -> (140.3434, 96.232)
  line L84 (140.4303, 95.9934) -> (140.5171, 95.7548)
  line L85 (141.3847, 96.3407) -> (140.4303, 95.9934)
  line L86 (141.2978, 96.5793) -> (141.3847, 96.3407)
  line L87 (141.7321, 95.3863) -> (140.7777, 95.0389)
  line L88 (141.9926, 94.6705) -> (141.7321, 95.3863)
  line L89 (141.8408, 94.3451) -> (141.9926, 94.6705)
  line L90 (141.125, 94.0845) -> (141.8408, 94.3451)
  line L91 (141.2987, 93.6073) -> (142.7303, 94.1284)
  line L92 (141.5593, 92.8915) -> (141.2987, 93.6073)
  line L93 (141.8847, 92.7397) -> (141.5593, 92.8915)
  line L94 (142.1233, 92.8266) -> (141.8847, 92.7397)
  line L95 (142.3619, 92.9134) -> (142.1233, 92.8266)
  line L96 (142.5137, 93.2389) -> (142.3619, 92.9134)
  line L97 (142.2531, 93.9547) -> (142.5137, 93.2389)
  line L98 (143.0347, 91.8072) -> (142.8611, 92.2845)
  line L99 (142.883, 91.4818) -> (143.0347, 91.8072)
  line L100 (142.1672, 91.2213) -> (142.883, 91.4818)
  line L101 (141.9066, 91.9371) -> (142.1672, 91.2213)
  line L102 (142.0584, 92.2625) -> (141.9066, 91.9371)
  line L103 (142.3838, 92.1108) -> (142.0584, 92.2625)
  line L104 (142.6444, 91.395) -> (142.3838, 92.1108)
  line L105 (142.5146, 90.2668) -> (142.3409, 90.7441)
  line L106 (142.4277, 90.5055) -> (142.5146, 90.2668)
  line L107 (143.8593, 91.0265) -> (142.4277, 90.5055)
  line L108 (143.7725, 91.2651) -> (143.8593, 91.0265)
  line L109 (142.9488, 89.0738) -> (142.7751, 89.551)
  line L110 (142.8619, 89.3124) -> (142.9488, 89.0738)
  line L111 (144.2936, 89.8335) -> (142.8619, 89.3124)
  line L112 (144.2067, 90.0721) -> (144.2936, 89.8335)
  line L113 (143.3941, 98.5102) -> (143.2424, 98.1848)
  line L114 (143.2204, 98.9875) -> (143.3941, 98.5102)
  line L115 (142.895, 99.1392) -> (143.2204, 98.9875)
  line L116 (142.6564, 99.0524) -> (142.895, 99.1392)
  line L117 (142.5046, 98.7269) -> (142.6564, 99.0524)
  line L118 (142.6783, 98.2497) -> (142.5046, 98.7269)
  line L119 (142.5265, 97.9243) -> (142.6783, 98.2497)
  line L120 (142.2879, 97.8374) -> (142.5265, 97.9243)
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sketch "Target Cutout" plane through (0, 0, 0) normal (0, 0, 1) x axis (1, 0, 0)
  line L1 (62, -2) -> (47, -2)
  line L2 (47, -2) -> (47, 107)
  line L3 (62, 107) -> (62, -2)
  line L4 (47, 107) -> (62, 107)
  line L5 (29, 107) -> (29, -2)
  line L6 (47, 107) -> (29, 107)
  line L7 (29, -2) -> (47, -2)
  circle C1 centre (37, 32.5) radius 2
  circle C2 centre (37, 72.5) radius 2
  circle C3 centre (57, 3) radius 1.4
  circle C4 centre (37, 92.5) radius 2
  circle C5 centre (57, 3) radius 1.9
  circle C6 centre (37, 12.5) radius 2
  circle C7 centre (57, 77.5) radius 4
  circle C8 centre (57, 77.5) radius 1.9
  circle C9 centre (57, 3) radius 4
  circle C10 centre (57, 77.5) radius 1.4
  circle C11 centre (37, 52.5) radius 2
  concentric C3 C5
  concentric C7 C8
  perpendicular L2 L6
  perpendicular L5 L7
  dimension "d439" diameter C7 = 8
  dimension "d440" diameter C9 = 8
  dimension "d441" diameter C5 = 3.8
  dimension "d442" diameter C8 = 3.8
sketch "Kickers" plane through (0, 0, 0) normal (0, 0, 1) x axis (1, 0, 0)
  line L1 (-17.9996, 16.5424) -> (-17.9993, 16.9967)
  line L2 (-17.9995, 13.0183) -> (18.0005, 13.0189)
  line L3 (18.0004, 16.543) -> (-17.9996, 16.5424)
  line L4 (30, -4.4) -> (30, -17)
  line L5 (-26.4995, -16.9989) -> (-17.9995, -16.9987)
  line L6 (15.0006, -16.5331) -> (15, 16.543)
  line L7 (30, 4.5) -> (29.8333, 4.4)
  line L8 (-14.9977, 16.5424) -> (-14.9977, 16.5374)
  line L9 (25.9, -8.2) -> (25.9, -4.4)
  line L10 (-17.9995, -16.9987) -> (-17.999, -16.5011)
  line L11 (-26.5001, 16.9965) -> (-17.9993, 16.9967)
  line L12 (-17.999, -16.5011) -> (-17.9996, 16.9967)
  line L13 (18.001, -16.536) -> (-17.999, -16.5011)
  line L14 (-17.999, -16.5011) -> (-17.999, -16.5011)
  line L15 (-26.5001, 16.9965) -> (-26.4995, -16.9989)
  line L16 (18, -12.9962) -> (-17.999, -12.999)
  line L17 (18.001, 17.0002) -> (18.0004, -16.9998)
  line L18 (18.001, -12.9962) -> (18, -12.9962)
  line L19 (18.5, -4.4) -> (18.5, -8.2)
  line L20 (30, -4.4) -> (29.5, -4.4)
  line L21 (26.5, -4.3) -> (26.625, -4.4)
  line L22 (18.001, -16.9998) -> (18.0004, 16.543)
  line L23 (26.625, 4.4) -> (26.5, 4.3)
  line L24 (22.1, 4.4) -> (22.1, 8.4)
  line L25 (29, 17) -> (30, 17)
  line L26 (22.1, -8.2) -> (22.1, -4.4)
  line L27 (26.5, 4.3) -> (26.5, -4.3)
  line L28 (18.5, 4.4) -> (29.5, 4.4)
  line L29 (30, 17) -> (30, 4.4)
  line L30 (30, -17) -> (29, -17)
  line L31 (29.5, -8.2) -> (29.5, -4.4)
  line L32 (18.5, 8.4) -> (29.5, 8.4)
  line L33 (18.5, -4.4) -> (29.5, -4.4)
  line L34 (29.5, 4.4) -> (29.5, 8.4)
  line L35 (30, 4.4) -> (29.8333, 4.4)
  line L36 (-14.9983, -16.504) -> (-14.9977, 16.5374)
  line L37 (30, -4.5) -> (29.5, -4.4)
  line L38 (18.5, 8.4) -> (18.5, 4.4)
  line L39 (25.9, 4.2) -> (25.9, -4.4)
  line L40 (18.0004, -16.9998) -> (29, -17)
  line L41 (18.5, -8.2) -> (29.5, -8.2)
  line L42 (25.9, 4.2) -> (25.9, 8.4)
  line L43 (18.001, 17.0002) -> (29, 17)
  line L44 (18.5, 4.4) -> (29.8333, 4.4)
  circle C1 centre (-14.5, -7) radius 3.5
  circle C2 centre (-14.5, 7) radius 2.1
  circle C3 centre (-14.5, 7) radius 3.5
  circle C4 centre (-14.5, -7) radius 2.1
  circle C5 centre (21.5, 13.2) radius 2.1
  circle C6 centre (21.5, 13.2) radius 3.5
  circle C7 centre (21.5, -13.2) radius 2.1
  circle C8 centre (21.5, -13.2) radius 3.5
  point P48 (25.9, -4.4)
  point P30 (22.1, -4.4)
  point P57 (25.9, 8.4)
  point P34 (22.1, 8.4)
  point P53 (30, -4.5)
  point P52 (30, 4.5)
  point P19 (22.1, 4.4)
  point P50 (30, 4.4)
  point P15 (26.625, -4.4)
  point P13 (26.625, 4.4)
  point P64 (18.001, -16.9998)
  coincident P48 L33
  coincident P30 L33
  coincident P57 L32
  coincident P34 L32
  concentric C5 C6
  concentric C7 C8
  coincident P53 L4
  coincident P52 L4
  coincident P19 L44
  coincident P50 L4
  coincident P15 L33
  coincident P13 L44
  coincident L40 P64
  dimension "d447" diameter C7 = 4.2
  dimension "d448" diameter C5 = 4.2
sketch "Posts Top" plane through (0, 0, 0) normal (0, 0, 1) x axis (1, 0, 0)
  line L1 (113.7698, 340.046) -> (146.2579, 250.7857)
  line L2 (139.3676, 244.5817) -> (109.5231, 259.1378)
  line L3 (104.4986, 341.9925) -> (107.3612, 343.0344)
  line L4 (101.6607, 271.6245) -> (101.2088, 337.2596)
  line L5 (250, 300) -> (250, 150)
  line L6 (250, 125) -> (250, 350)
  line L7 (395.5014, 341.9925) -> (392.6388, 343.0344)
  line L8 (398.3393, 271.6245) -> (398.7912, 337.2596)
  line L9 (386.2302, 340.046) -> (353.7421, 250.7857)
  line L10 (360.6324, 244.5817) -> (390.4769, 259.1378)
  circle C1 centre (108.4737, 337.0542) radius 2.25
  arc A1 centre (115.6603, 271.7209) radius 14 clockwise from (109.5231, 259.1378) to (101.6607, 271.6245)
  arc A2 centre (141.5594, 249.0756) radius 5 clockwise from (146.2579, 250.7857) to (139.3676, 244.5817)
  circle C2 centre (139.5975, 251.5422) radius 4
  circle C3 centre (109.092, 268.1077) radius 4
  circle C4 centre (109.092, 268.1077) radius 2.25
  circle C5 centre (108.4737, 337.0542) radius 4
  arc A3 centre (106.2087, 337.294) radius 5 clockwise from (101.2088, 337.2596) to (104.4986, 341.9925)
  arc A4 centre (109.0713, 338.3359) radius 5 clockwise from (107.3612, 343.0344) to (113.7698, 340.046)
  circle C6 centre (139.5975, 251.5422) radius 2.25
  circle C7 centre (390.908, 268.1077) radius 4
  arc A5 centre (393.7913, 337.294) radius 5 clockwise from (395.5014, 341.9925) to (398.7912, 337.2596)
  arc A6 centre (384.3397, 271.7209) radius 14 clockwise from (398.3393, 271.6245) to (390.4769, 259.1378)
  arc A7 centre (390.9287, 338.3359) radius 5 clockwise from (386.2302, 340.046) to (392.6388, 343.0344)
  circle C8 centre (391.5263, 337.0542) radius 4
  circle C9 centre (390.908, 268.1077) radius 2.25
  circle C10 centre (360.4025, 251.5422) radius 4
  circle C11 centre (391.5263, 337.0542) radius 2.25
  circle C12 centre (360.4025, 251.5422) radius 2.25
  arc A8 centre (358.4406, 249.0756) radius 5 clockwise from (360.6324, 244.5817) to (353.7421, 250.7857)
  point P3 (139.3676, 244.5817)
  point P25 (360.6324, 244.5817)
  point P5 (101.6607, 271.6245)
  point P26 (398.3393, 271.6245)
  point P6 (109.5231, 259.1378)
  point P28 (390.4769, 259.1378)
  point P11 (104.4986, 341.9925)
  point P29 (395.5014, 341.9925)
  point P12 (101.2088, 337.2596)
  point P27 (398.7912, 337.2596)
  point P16 (113.7698, 340.046)
  point P35 (386.2302, 340.046)
  point P18 (146.2579, 250.7857)
  point P40 (353.7421, 250.7857)
  point P19 (107.3612, 343.0344)
  point P37 (392.6388, 343.0344)
  perpendicular L1 L3
  tangent L1 A4
  tangent L3 A4
  tangent L3 A3
  tangent L4 A3
  concentric C3 C4
  concentric C1 C5
  tangent A1 L4
  tangent A1 L2
  tangent L2 A2
  tangent L1 A2
  parallel L5 L6
  symmetric P3 L6 P25
  symmetric P5 L6 P26
  symmetric P6 L6 P28
  symmetric P11 L6 P29
  symmetric P12 L6 P27
  symmetric P16 L6 P35
  symmetric P18 L6 P40
  symmetric P19 L6 P37
  symmetric C1 L6 C11
  symmetric A1 L6 A6
  symmetric A2 L6 A8
  symmetric C2 L6 C10
  symmetric C3 L6 C7
  symmetric C4 L6 C9
  symmetric C5 L6 C8
  symmetric A3 L6 A5
  symmetric A4 L6 A7
  symmetric C6 L6 C12
  dimension "d449" radius A4 = 5
  dimension "d450" radius A3 = 5
  dimension "d451" diameter C3 = 8
  dimension "d452" diameter C5 = 8
  dimension "d453" diameter C2 = 8
  dimension "d454" radius A1 = 14
  dimension "d455" radius A2 = 5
